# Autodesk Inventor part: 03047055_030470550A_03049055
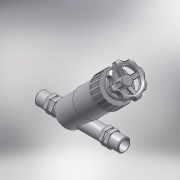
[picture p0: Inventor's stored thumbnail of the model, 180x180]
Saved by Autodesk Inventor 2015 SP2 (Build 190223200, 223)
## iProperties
Created: 2017-05
Part Number: 03047055_030470550A_03049055
Material: Generic
Description: PLASSON ANGLE SEAT VALVE 1/2"
Document SubType Name: Modeling
Designer: KIM
Mass: 184.302 g
Surface Area: 375.869 cm^2
Volume: 184.302 cm^3
Density: 1 g/cm^3
Appearance: Default
Author: KIM
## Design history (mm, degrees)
derived "03047.ipt"
feature "Solid1::03047.ipt"
tag "TaggingFeature1"
body "Solid1"
other parameters: "d0" = 135, "d1" = 20.955, "d2" = 22, "d3" = 16.764, "d4" = 16, "d5" = 16, "d6" = 13.5, "d8" = 1.35, "d12" = 0, "d14" = -6.75, "d15" = 2.7, "d16" = 0, "d17" = 33.561, "d19" = 106.785, "d20" = 40.68, "d21" = 135 deg, "d22" = 43.2225, "d23" = 20.34, "d24" = 48.3075, "d25" = 12.204, "d26" = 90 deg, "d27" = 35.595, "d28" = 70 deg, "d29" = 15.255, "d30" = 12.204, "d31" = 15.255, "d32" = 50.85, "d33" = 35.595, "d34" = 135 deg, "d35" = 2, "d36" = 101.7, "d39" = 47.25, "d40" = 1.13, "d42" = 2, "d43" = 3.39, "d44" = 3.39, "d46" = 0, "d48" = 360 deg, "d50" = 0.565, "d51" = 0.565, "d53" = 360 deg, "d69" = 43.2225, "d70" = 3.39, "d71" = 3.39, "d72" = 6.78, "d74" = 0, "d75" = 0.565, "d77" = 360 deg, "d80" = 46.85828, "d81" = 4.52, "d82" = 2.26, "d83" = 18.306, "d84" = 0, "d86" = 360 deg, "d88" = 1.13, "d89" = 4.068, "d90" = 0.565, "d91" = 113, "H_" = 135, "R_" = 20.955, "E_" = 22, "l_2" = 16, "A_" = 113, "d13" = 13.5, "d67" = 50.85, "d68" = 35.595, "d79" = 48.3075
